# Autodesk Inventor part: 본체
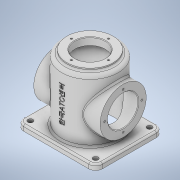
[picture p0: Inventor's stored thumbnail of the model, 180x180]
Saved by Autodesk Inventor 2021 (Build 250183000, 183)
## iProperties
Created: 2021-02
Part Number: 본체
Material: 알루미늄 6061
Document SubType Name: Modeling
Designer: 201-12
Density: 2.7 g/cm^3
Appearance: 기본값
Mass: 1235.53 g
Surface Area: 1067.61 cm^2
Volume: 457.603 cm^3
Author: 201-12
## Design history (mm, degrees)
sketch "스케치1"
  geometry: L1 (-70, 60)-(70, 60); L2 (70, 60)-(70, -60); L3 (70, -60)-(-70, -60); L4 (-70, -60)-(-70, 60); L5 (-70, 60)-(70, -60); L6 (70, 60)-(-70, -60); 1 further point
  constraints: 12 end point, 2 midpoint, 2 parallel, 1 horizontal, 1 perpendicular
  dimensions: "d0" = 140 distance of L2.end L3.end; "d1" = 120 distance of L1.end L2.end
extrude "돌출1" new body sketch "스케치1" distance "d2" = 10; taper "d3" = 0 deg
sketch "스케치2"
  geometry: C1 r 50 at (0, 0); 1 further point
  constraints: 1 centre point, 1 coincident
  dimensions: "d4" = 100 diameter of C1
extrude "돌출2" join sketch "스케치2" distance "d5" = 110; taper "d6" = 0 deg
sketch "스케치3"
  geometry: C1 r 50 at (0, 0) reference; C2 r 41 at (0, 0); 1 further point
  constraints: 1 centre point, 1 coincident
  dimensions: "d7" = 82 diameter of C2
extrude "돌출3" join sketch "스케치3" distance "d8" = 5; taper "d9" = 0 deg
sketch "스케치4"
  geometry: L1 (0, 60)-(0, -60) reference; L2 (0, -60)-(0, 60) reference; C1 r 41 at (60, 0); 1 further point
  constraints: 1 centre point, 1 horizontal alignment
  dimensions: "d10" = 82 diameter of C1; "d11" = 60 distance of point (0, 0) C1.centre
extrude "돌출4" join sketch "스케치4" stored distance "d12" = 118; taper "d13" = 0 deg
sketch "스케치5"
  geometry: L1 (41, 125)-(-41, 125) reference; L2 (0, 125)-(-27, 125); L3 (-27, 125)-(-27, 112); L4 (-27, 112)-(0, 112); L5 (0, 112)-(0, 125); L6 (0, 112)-(-42, 112); L7 (-42, 112)-(-42, 0); L8 (-42, 0)-(0, 0); L9 (0, 0)-(0, 112); 3 further points
  constraints: 16 end point, 4 parallel, 2 horizontal, 2 perpendicular, 1 midpoint
  dimensions: "d14" = 27 distance between parallel lines of L5 L3; "d15" = 42 distance between parallel lines of L9 L7; "d16" = 13 distance between parallel lines of L1 L4; "d17" = 112 distance between parallel lines of L4 L8
revolve "회전1" sketch "스케치5" stored, may be unused: angle "d18" = 90 deg
sketch "스케치6"
  geometry: C1 r 41 at (0, 0) reference; C2 r 27 at (0, 0); 1 further point
  constraints: 1 centre point, 1 coincident
  dimensions: "d19" = 54 diameter of C2
extrude "돌출5" cut sketch "스케치6" stored distance "d20" = 0; taper "d21" = 0 deg
sketch "스케치7"
  geometry: L1 (-33, 0)-(33, 0); L2 (0, 33)-(0, -33); C1 r 41 at (0, 0) reference; A1 r 33 centre (0, 0) between (-33, 0) and (33, 0); 7 further points
  constraints: 5 coincident, 4 end point, 4 midpoint, 4 point on circle, 1 centre point, 1 horizontal, 1 vertical
  dimensions: "d22" = 66 diameter of A1
hole "구멍1" sketch "스케치7" at (0, 33), (-33, 0), (33, 0), (0, -33) diameter "d23" = 3.242; stored, may be unused: countersink angle "d27" = 90 deg, drill point angle "d29" = 118 deg; dims "d24" = 8, "d25" = 4, "d26" = 2, "d28" = 10
sketch "스케치8"
  geometry: L1 (-33, 0)-(33, 0); L2 (0, 33)-(0, -33); C1 r 41 at (0, 0) reference; A1 r 33 centre (0, 0) between (-33, 0) and (33, 0); 7 further points
  constraints: 5 coincident, 4 end point, 4 midpoint, 4 point on circle, 1 centre point, 1 horizontal, 1 vertical
  dimensions: "d30" = 66 diameter of A1
hole "구멍2" sketch "스케치8" at (0, 33), (-33, 0), (0, -33), (33, 0) diameter "d31" = 3.242; stored, may be unused: countersink angle "d35" = 90 deg, drill point angle "d37" = 118 deg; dims "d32" = 8, "d33" = 4, "d34" = 2, "d36" = 10
fillet "모깎기1" dims "d38" = 12
sketch "스케치9"
  geometry: L1 (-58, -60)-(58, -60) reference; L2 (70, -48)-(70, 48) reference; L3 (58, 60)-(-58, 60) reference; L4 (-70, 48)-(-70, -48) reference; C1 r 50 at (0, 0) reference; A1 r 12 centre (-58, -48) between (-70, -48) and (-58, -60) reference; A2 r 12 centre (58, -48) between (58, -60) and (70, -48) reference; A3 r 12 centre (58, 48) between (70, 48) and (58, 60) reference; A4 r 12 centre (-58, 48) between (-58, 60) and (-70, 48) reference; 5 further points
  constraints: 4 coincident
hole "구멍3" sketch "스케치9" at (58, -48), (-58, -48), (-58, 48), (58, 48) diameter "d39" = 9; stored, may be unused: countersink angle "d43" = 90 deg, drill point angle "d45" = 0 deg; dims "d40" = 8, "d41" = 4, "d42" = 2, "d44" = 10
fillet "모깎기2" dims "d46" = 3
chamfer "모따기1" distance "d47" = 1; stored, may be unused: second distance "d48" = 2, angle "d49" = 45 deg
chamfer "모따기2" distance "d50" = 1; stored, may be unused: second distance "d51" = 2, angle "d52" = 45 deg
fillet "모깎기3" dims "d53" = 3
chamfer "모따기3" distance "d54" = 1; stored, may be unused: second distance "d55" = 2, angle "d56" = 45 deg
fillet "모깎기4" dims "d57" = 6
fillet "모깎기5" dims "d58" = 3
node "작업 평면1"
sketch "스케치10"
  geometry: L1 (-58, 0)-(58, 0) reference; 3 further points
  constraints: 1 midpoint, 1 vertical alignment, 1 other
  dimensions: "d62" = 66 distance of point (0, 66) point (0, 0)
feature "엠보싱1" sketch "스케치10" dims "d0" = 140, "d1" = 120, "d60" = 0.5, "d61" = 0
node "솔리드1"
mirror "미러1"
node "투영된 루프1"
node "투영된 루프2"
node "투영된 루프3"
feature "A9D066F2-1C7D-4E18-AEED-F7BC21143FA4" dims "d31" = 3.242, "d32" = 8, "d33" = 4, "d34" = 2, "d35" = 90 deg, "d36" = 10, "d37" = 118 deg
other parameters: "d59" = 104
